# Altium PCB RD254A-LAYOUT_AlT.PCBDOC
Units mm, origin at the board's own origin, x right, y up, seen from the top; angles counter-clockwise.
Board outline 65 x 55 mm, 2 copper layers (TOP, BOTTOM), stack 0 mm thick; 28 components, 15 nets, 110 pads, 0 vias.
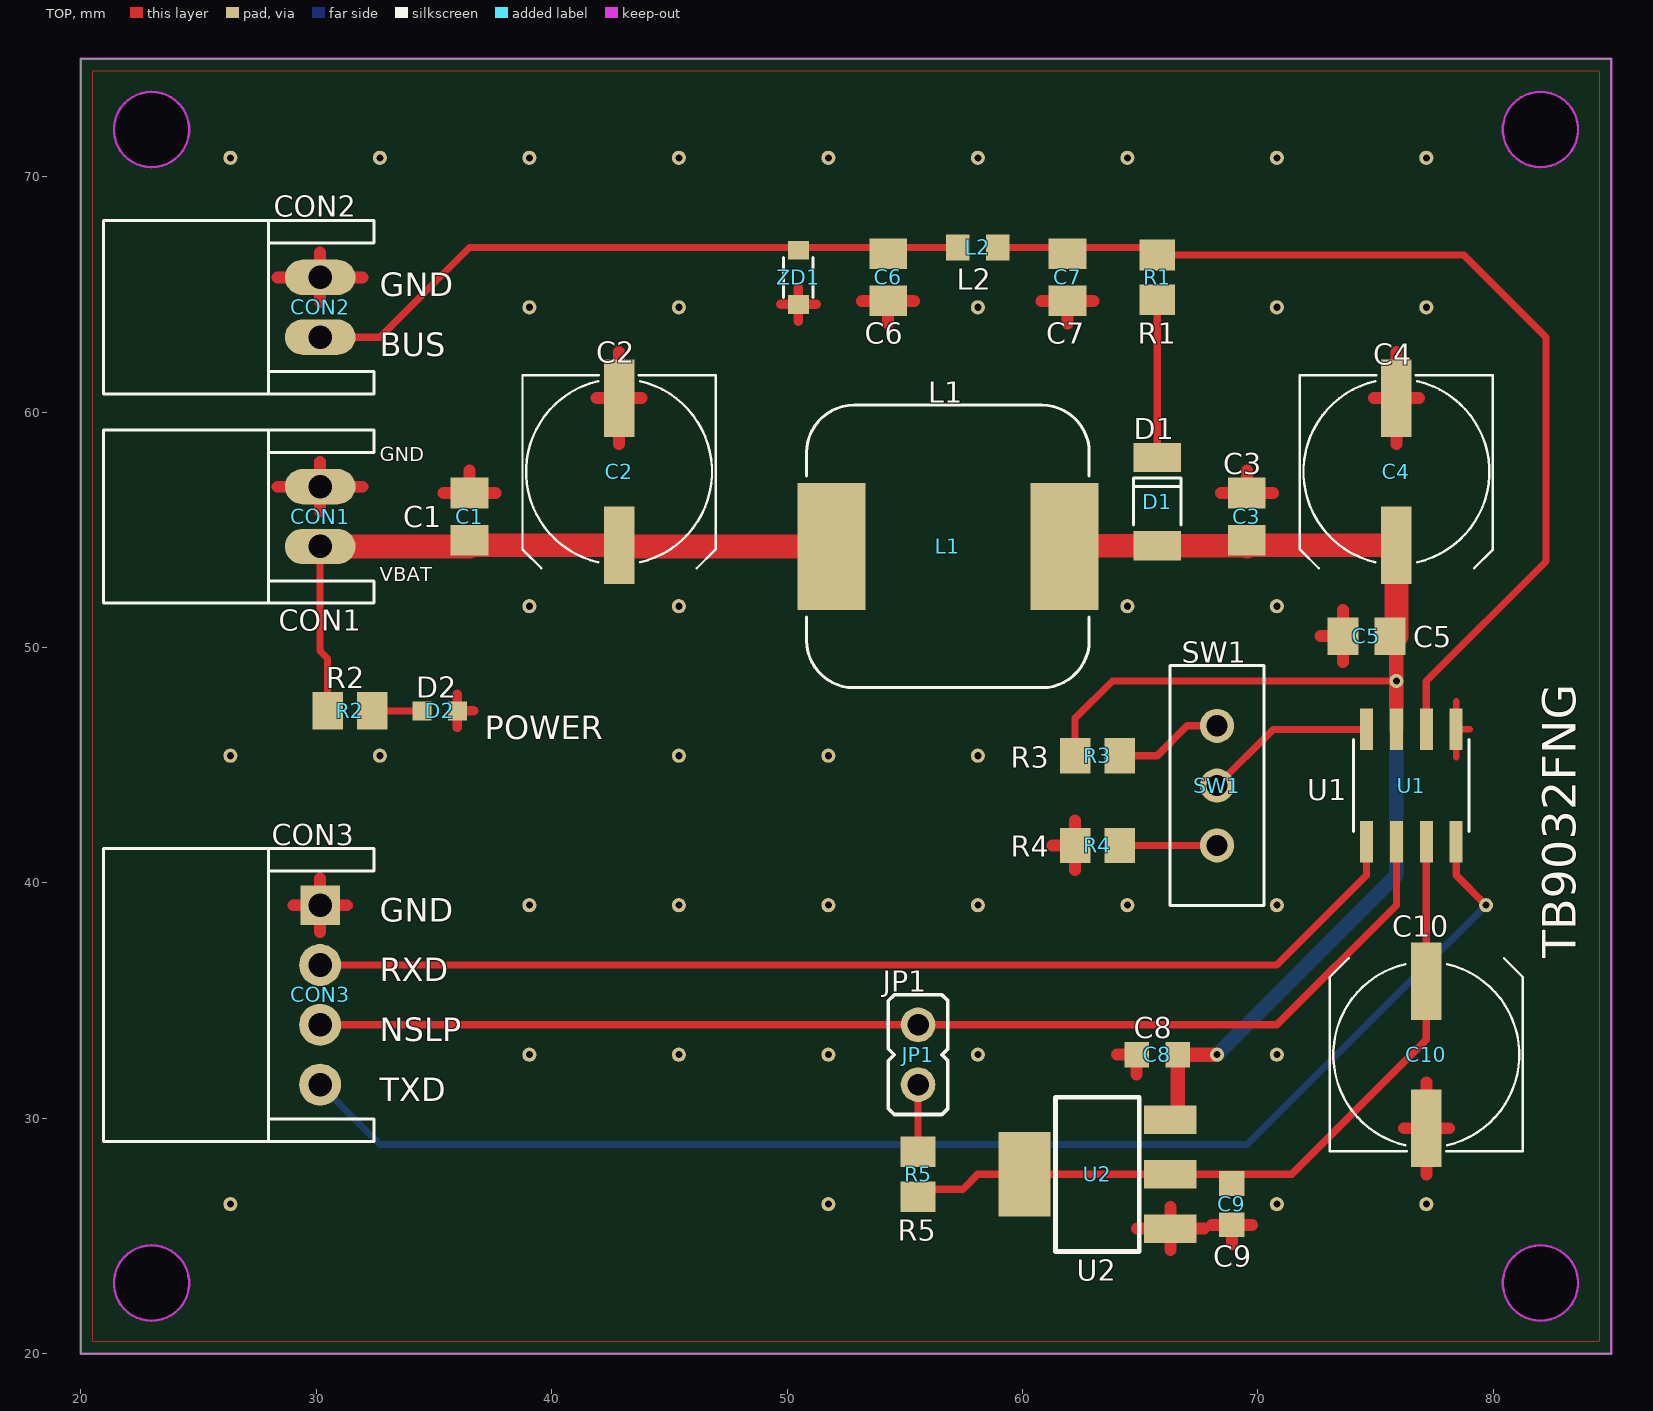
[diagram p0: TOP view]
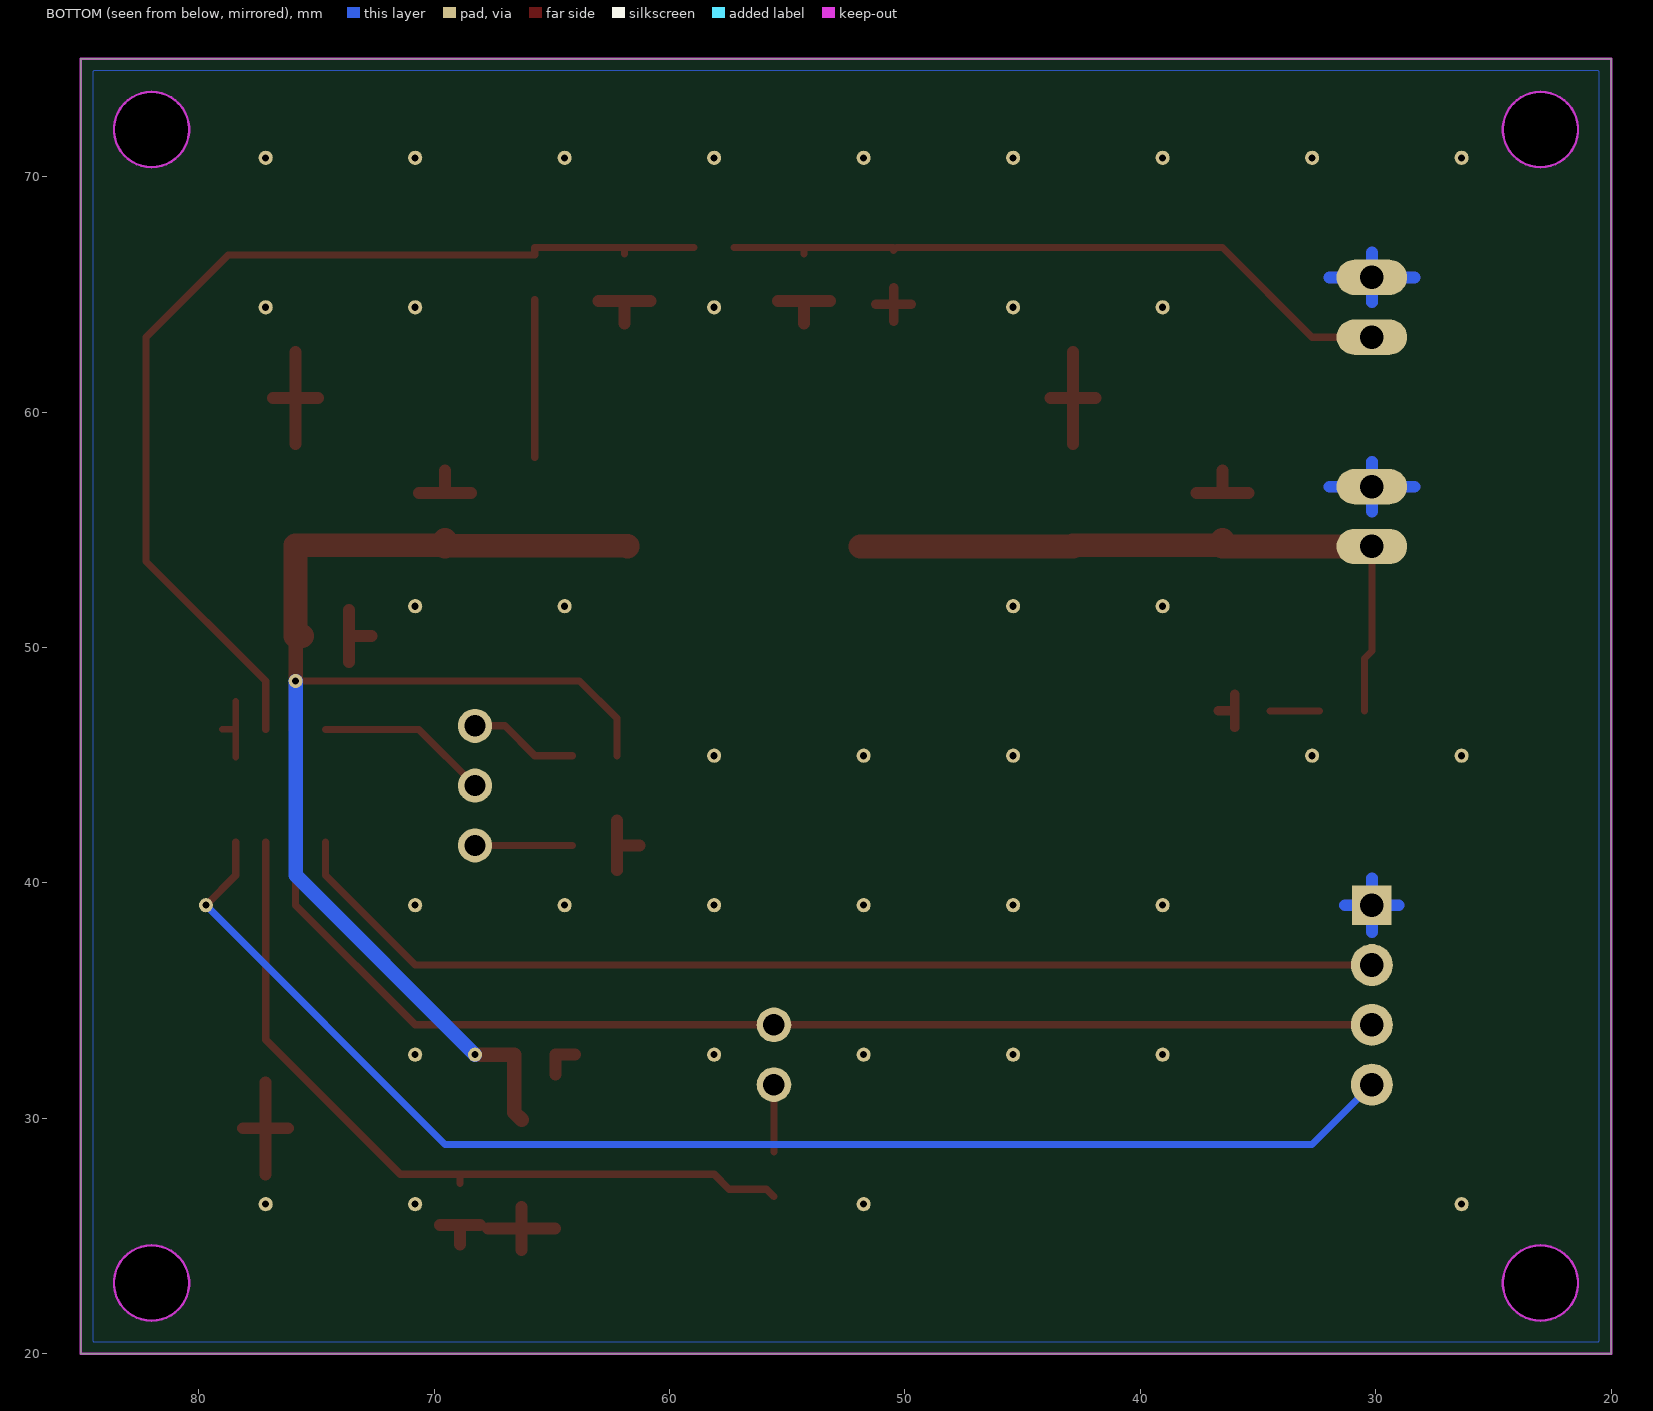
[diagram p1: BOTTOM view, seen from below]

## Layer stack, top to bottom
Top Solder: solder mask 0.0102, Solder Resist, Dk 3.5
TOP: signal copper (thickness not stored)
BOTTOM: signal copper (thickness not stored)
Bottom Solder: solder mask 0.0102, Solder Resist, Dk 3.5

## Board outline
20,20 20,75 85,75 85,20

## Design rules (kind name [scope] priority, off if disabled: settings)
AssemblyTestPointUsage [All] p0: scope1count=1 scope1_0_kind=Board scope1_0_value=Board scope2count=1 scope2_0_kind=Board scope2_0_value=Board commentlength=0
AssemblyTestpoint [All] p0: scope1count=1 scope1_0_kind=Board scope1_0_value=Board scope2count=1 scope2_0_kind=Board scope2_0_value=Board commentlength=0
Clearance [All] p0: scope1count=1 scope1_0_kind=Board scope1_0_value=Board scope2count=1 scope2_0_kind=Board scope2_0_value=Board commentlength=0 gap=0.254
Clearance [All] p1: gap=0.254 ignorepadtopadclearanceinfootprint=TRUE except(0.3: Arc-Hole Track-Hole SMDPad-Hole THPad-Hole Via-Hole Fill-Hole Poly-Hole Region-Hole Text-Hole)
ComponentClearance [All] p0: scope1count=1 scope1_0_kind=Board scope1_0_value=Board scope2count=1 scope2_0_kind=Board scope2_0_value=Board commentlength=0 gap=0.254 collisioncheckmode=3
DiffPairsRouting [All] p0: scope1count=1 scope1_0_kind=Board scope1_0_value=Board scope2count=1 scope2_0_kind=Board scope2_0_value=Board commentlength=0
FabricationTestPointUsage [All] p0: scope1count=1 scope1_0_kind=Board scope1_0_value=Board scope2count=1 scope2_0_kind=Board scope2_0_value=Board commentlength=0 valid=0 allowmultiple=FALSE
FabricationTestpoint [All] p0: scope1count=1 scope1_0_kind=Board scope1_0_value=Board scope2count=1 scope2_0_kind=Board scope2_0_value=Board commentlength=0 side=3 testpointundercomponent=TRUE minsize=1.016 maxsize=2.54 preferedsize=1.524 minholesize=0 maxholesize=1.016 preferedholesize=0.813 testpointgrid=0.025
FanoutControl Fanout_BGA [All] p0 off: scope1count=1 scope1_0_kind=Board scope1_0_value=Board scope2count=1 scope2_0_kind=Board scope2_0_value=Board commentlength=69 // Protel DXP Scope 1 Expression Was: IsBGA   Fanout_BGA (Default Rule)
FanoutControl Fanout_LCC [All] p0 off: scope1count=1 scope1_0_kind=Board scope1_0_value=Board scope2count=1 scope2_0_kind=Board scope2_0_value=Board commentlength=69 // Protel DXP Scope 1 Expression Was: IsLCC   Fanout_LCC (Default Rule)
FanoutControl Fanout_SOIC [All] p0 off: scope1count=1 scope1_0_kind=Board scope1_0_value=Board scope2count=1 scope2_0_kind=Board scope2_0_value=Board commentlength=71 // Protel DXP Scope 1 Expression Was: IsSOIC   Fanout_SOIC (Default Rule)
FanoutControl Fanout_Small [All] p0 off: scope1count=1 scope1_0_kind=Board scope1_0_value=Board scope2count=1 scope2_0_kind=Board scope2_0_value=Board commentlength=84 // Protel DXP Scope 1 Expression Was: (CompPinCount < 5)   Fanout_Small (Default Rule)
FanoutControl Fanout_Default [All] p0: scope1count=1 scope1_0_kind=Board scope1_0_value=Board scope2count=1 scope2_0_kind=Board scope2_0_value=Board commentlength=30 // Fanout_Default (Default Rule)
Height [All] p0: scope1count=1 scope1_0_kind=Board scope1_0_value=Board scope2count=1 scope2_0_kind=Board scope2_0_value=Board commentlength=0
HoleSize [All] p0: scope1count=1 scope1_0_kind=Board scope1_0_value=Board scope2count=1 scope2_0_kind=Board scope2_0_value=Board commentlength=0 absolutevalues=TRUE maxlimit=100 minlimit=0.001 maxpercent=80.000 minpercent=20.000
HoleSize [All] p1: absolutevalues=TRUE maxlimit=100 minlimit=0.001 maxpercent=80.000 minpercent=20.000
HoleToHoleClearance [All] p0: scope1count=1 scope1_0_kind=Board scope1_0_value=Board scope2count=1 scope2_0_kind=Board scope2_0_value=Board commentlength=0
HoleToHoleClearance [All] p1: gap=0.4 allowstackedmicrovias=FALSE
LayerPairs [All] p0: scope1count=1 scope1_0_kind=Board scope1_0_value=Board scope2count=1 scope2_0_kind=Board scope2_0_value=Board commentlength=0 enforce=TRUE
MinimumSolderMaskSliver [All] p0: scope1count=1 scope1_0_kind=Board scope1_0_value=Board scope2count=1 scope2_0_kind=Board scope2_0_value=Board commentlength=0
MinimumSolderMaskSliver [All] p1: minsoldermaskwidth=0.1
NetAntennae [All] p0: scope1count=1 scope1_0_kind=Board scope1_0_value=Board scope2count=1 scope2_0_kind=Board scope2_0_value=Board commentlength=0
NetAntennae [All] p1: netantennaetolerance=100
PasteMaskExpansion [All] p0: scope1count=1 scope1_0_kind=Board scope1_0_value=Board scope2count=1 scope2_0_kind=Board scope2_0_value=Board commentlength=0 expansion=0
PlaneClearance [All] p0: scope1count=1 scope1_0_kind=Board scope1_0_value=Board scope2count=1 scope2_0_kind=Board scope2_0_value=Board commentlength=0 clearance=0.001
PlaneClearance [All] p1: clearance=0.001
PlaneConnect [All] p0: scope1count=1 scope1_0_kind=Board scope1_0_value=Board scope2count=1 scope2_0_kind=Board scope2_0_value=Board commentlength=0 planeconnectstyle=Direct reliefexpansion=0.508 reliefentries=4 reliefconductorwidth=0.254 reliefairgap=0.254
PlaneConnect [All] p1: planeconnectstyle=Direct reliefexpansion=0.508 reliefentries=4 reliefconductorwidth=0.254 reliefairgap=0.254
PolygonConnect [All] p0: scope1count=1 scope1_0_kind=Board scope1_0_value=Board scope2count=1 scope2_0_kind=Board scope2_0_value=Board commentlength=0 connectstyle=Direct reliefconductorwidth=0.254 reliefentries=4 polygonreliefangle="90 Angle"
PolygonConnect [All] p1: connectstyle=Direct reliefconductorwidth=0.254 reliefentries=4 polygonreliefangle="90 Angle" airgapwidth=0.254
RoutingCorners [All] p0: scope1count=1 scope1_0_kind=Board scope1_0_value=Board scope2count=1 scope2_0_kind=Board scope2_0_value=Board commentlength=0 cornerstyle=45-Degree minsetback=2.54 maxsetback=2.54
RoutingLayers [All] p0: scope1count=1 scope1_0_kind=Board scope1_0_value=Board scope2count=1 scope2_0_kind=Board scope2_0_value=Board commentlength=0 top layer=Automatic bottom layer=Automatic
RoutingPriority [All] p0: scope1count=1 scope1_0_kind=Board scope1_0_value=Board scope2count=1 scope2_0_kind=Board scope2_0_value=Board commentlength=0
RoutingTopology [All] p0: scope1count=1 scope1_0_kind=Board scope1_0_value=Board scope2count=1 scope2_0_kind=Board scope2_0_value=Board commentlength=0 topology=Shortest
RoutingVias [All] p0: scope1count=1 scope1_0_kind=Board scope1_0_value=Board scope2count=1 scope2_0_kind=Board scope2_0_value=Board commentlength=0 holewidth=0.1 width=0.1 viastyle="Through Hole" minholewidth=0.001 minwidth=0.001 maxholewidth=100 maxwidth=100
RoutingVias [All] p1: holewidth=0.1 width=0.1 viastyle="Through Hole" minholewidth=0.001 minwidth=0.001 maxholewidth=100 maxwidth=100
ShortCircuit [All] p0: scope1count=1 scope1_0_kind=Board scope1_0_value=Board scope2count=1 scope2_0_kind=Board scope2_0_value=Board commentlength=0 allowed=FALSE
SilkToBoardRegionClearance [All] p0: scope1count=1 scope1_0_kind=Board scope1_0_value=Board scope2count=1 scope2_0_kind=Board scope2_0_value=Board commentlength=0
SilkToSilkClearance [All] p0: scope1count=1 scope1_0_kind=Board scope1_0_value=Board scope2count=1 scope2_0_kind=Board scope2_0_value=Board commentlength=0
SilkToSilkClearance [All] p1: silktosilkclearance=0.001
SilkToSolderMaskClearance [All] p0 off: scope1count=1 scope1_0_kind=Board scope1_0_value=Board scope2count=1 scope2_0_kind=Board scope2_0_value=Board commentlength=44 // Protel DXP Scope 1 Expression Was: IsPad
SilkToSolderMaskClearance [IsPad] p1: minsilkscreentomaskgap=0 clearancetoexposedcopper=TRUE
SolderMaskExpansion [All] p0: scope1count=1 scope1_0_kind=Board scope1_0_value=Board scope2count=1 scope2_0_kind=Board scope2_0_value=Board commentlength=0 expansion=0.001
SolderMaskExpansion [All] p1: expansion=0.001
UnRoutedNet [All] p0: scope1count=1 scope1_0_kind=Board scope1_0_value=Board scope2count=1 scope2_0_kind=Board scope2_0_value=Board commentlength=0
UnpouredPolygon [All] p0: scope1count=1 scope1_0_kind=Board scope1_0_value=Board scope2count=1 scope2_0_kind=Board scope2_0_value=Board commentlength=0
Width [All] p0: scope1count=1 scope1_0_kind=Board scope1_0_value=Board scope2count=1 scope2_0_kind=Board scope2_0_value=Board commentlength=0 maxlimit=1000 minlimit=2539.975 preferedwidth=0
Width [All] p1: maxlimit=1000 minlimit=2539.975 preferedwidth=0 toplayer_minwidth=0 bottomlayer_minwidth=0 minimp=50.000000 maximp=50.000000 favimp=50.000000
22 further rules are at their usual default settings.

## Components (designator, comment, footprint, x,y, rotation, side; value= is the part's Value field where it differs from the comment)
C1 "C0805K" C0805K 36.51,55.56 r90 top
C2 "UD-8X10_NICHICON_01" UD-8X10_NICHICON_01 42.86,57.465 r270 top
C3 "C0805K" C0805K 69.53,55.56 r90 top
C4 "UD-8X10_NICHICON_01" UD-8X10_NICHICON_01 75.88,57.465 r270 top
C5 "C0805K" C0805K 74.61,50.48 r180 top
C6 "C0805K" C0805K 54.29,65.72 r270 top
C7 "C0805K" C0805K 61.91,65.72 r270 top
C8 "C0603K" C0603K 65.72,32.7 r0 top
C9 "C0603K" C0603K 68.895,26.35 r90 top
C10 "UD-8X10_NICHICON_01" UD-8X10_NICHICON_01 77.15,32.7 r90 top
cam2 "A4L-LOC" A4L-LOC -68,-49 r0 top
CON1 "S2B-XH-A" S2B-XH-A 30.16,55.56 r90 top
CON2 "S2B-XH-A" S2B-XH-A 30.16,64.45 r90 top
CON3 "S4B-XH-A" S4B-XH-A 30.16,35.24 r90 top
D1 "LL4148" LL4148 65.72,56.195 r90 top
D2 "CHIP-LED0603" CHIP-LED0603 35.24,47.305 r270 top
JP1 "JP1" JP1 55.56,32.7 r0 top
L1 "7447709222" 7447709222 56.83,54.29 r270 top
L2 "R0603" R0603 58.1,66.99 r0 top
R1 "R0805" R0805 65.72,65.72 r270 top
R2 "M0805" M0805 31.43,47.305 r180 top
R3 "R0805" R0805 63.18,45.4 r0 top
R4 "R0805" R0805 63.18,41.59 r180 top
R5 "R0805" R0805 55.56,27.62 r90 top
SW1 "SS-12SDP2" SS-12SDP2 68.26,44.13 r0 top
U1 "P-SOP8-0405-1_27-002" P-SOP8-0405-1_27-002 76.515,44.13 r90 top
U2 "SOT223" SOT223 63.18,27.62 r90 top
ZD1 "USC" USC 50.48,65.72 r270 top

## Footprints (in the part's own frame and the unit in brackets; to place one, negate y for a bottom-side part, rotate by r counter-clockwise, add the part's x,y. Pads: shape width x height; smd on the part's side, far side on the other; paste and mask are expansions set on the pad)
7447709222 [mm] "KC00080BKP"
  rect 5.4x2.9 smd paste-5.603 mask+0: 1(0,-4.95) 2(0,4.95)
  silkscreen extent -6,-6 6,6
A4L-LOC [mm] "KC00080BKP"
C0603K [mm] "KC00080BKP"
  rect 1.05x1.08 smd paste-1.283 mask+0: 1(-0.875,0) 2(0.875,0)
C0805K [mm] "KC00080BKP"
  rect 1.3x1.6 smd paste-1.803 mask+0: 1(-1,0) 2(1,0)
CHIP-LED0603 [mm] "KC00080BKP"
  rect 0.8x0.8 smd paste-1.003 mask+0: A(0,-0.75) C(0,0.75)
JP1 [mm] "KC00080BKP"
  round 1.47 / inner round 0 / far side round 1.47 hole 0.914 paste-1.67 mask+0: 1(0,-1.27) 2(0,1.27)
  silkscreen extent -1.27,-2.54 1.27,2.54
LL4148 [mm] "KC00080BKP"
  rect 1.25x2 smd paste-2.203 mask+0: A(-1.875,0) K(1.875,0)
  silkscreen extent -1,-1 1,1
M0805 [mm] "KC00080BKP"
  rect 1.3x1.6 smd paste-1.803 mask+0: 1(-0.95,0) 2(0.95,0)
P-SOP8-0405-1_27-002 [mm] "KC00080BKP"
  rect 1.77x0.55 smd paste-1.973 mask+0: 1(-2.39,1.905) 2(-2.39,0.635) 3(-2.39,-0.635) 4(-2.39,-1.905) 5(2.39,-1.905) 6(2.39,-0.635) 7(2.39,0.635) 8(2.39,1.905)
  silkscreen extent -1.95,-2.45 1.95,2.45
R0603 [mm] "KC00080BKP"
  rect 1x1.1 smd paste-1.303 mask+0: 1(-0.85,0) 2(0.85,0)
R0805 [mm] "KC00080BKP"
  rect 1.3x1.5 smd paste-1.703 mask+0: 1(-0.95,0) 2(0.95,0)
S2B-XH-A [mm] "KC00080BKP"
  oval 1.5x3 / inner round 0 / far side oval 1.5x3 hole 1 paste-3.203 mask+0: 1(1.27,0) 2(-1.27,0)
  silkscreen extent -3.68,-2.3 3.68,9.2
S4B-XH-A [mm] "KC00080BKP"
  rect 1.676x1.676 / inner round 0 / far side rect 1.676x1.676 hole 1 paste-1.88 mask+0: 1(3.81,0)
  round 1.78 / inner round 0 / far side round 1.78 hole 1 paste-1.98 mask+0: 2(1.27,0) 3(-1.27,0) 4(-3.81,0)
  silkscreen extent -6.22,-2.3 6.22,9.2
SOT223 [mm] "KC00080BKP"
  rect 1.219x2.235 smd paste-2.438 mask+0: 1(-2.311,-3.099) 2(0,-3.099) 3(2.311,-3.099)
  rect 3.6x2.2 smd paste-3.803 mask+0: TAB(0,3.099)
  silkscreen extent -3.28,-1.78 3.28,1.78
SS-12SDP2 [mm] "KC00080BKP"
  round 1.45 / inner round 0 / far side round 1.45 hole 0.9 paste-1.65 mask+0: 1(0,2.54) 2(0,0) 3(0,-2.54)
  silkscreen extent -2,-5.1 2,5.1
UD-8X10_NICHICON_01 [mm] "KC00080BKP"
  rect 3.3x1.3 smd paste-3.503 mask+0: 1(-3.125,0) 2(3.125,0)
  silkscreen extent -4.1,-4.1 4.1,4.1
USC [mm] "KC00080BKP"
  rect 0.8x0.9 smd paste-1.103 mask+0: 1(-1.15,0) 2(1.15,0)
  silkscreen extent -0.85,-0.63 0.85,0.63

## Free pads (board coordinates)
  round 0 hole 3.2 unplated paste-3.4 mask+0: ""(23,23) ""(23,72) ""(82,23) ""(82,72)
  round 0.6 / inner round 0 / far side round 0.6 hole 0.3 paste-0.6 mask+0: ""(26.35,26.35) ""(26.35,45.4) ""(26.35,70.8) ""(32.7,45.4) ""(32.7,70.8) ""(39.05,32.7) ""(39.05,39.05) ""(39.05,51.75) ""(39.05,64.45) ""(39.05,70.8) ""(45.4,32.7) ""(45.4,39.05) ""(45.4,45.4) ""(45.4,51.75) ""(45.4,64.45) ""(45.4,70.8) ""(51.75,26.35) ""(51.75,32.7) ""(51.75,39.05) ""(51.75,45.4) ""(51.75,70.8) ""(58.1,32.7) ""(58.1,39.05) ""(58.1,45.4) ""(58.1,64.45) ""(58.1,70.8) ""(64.45,39.05) ""(64.45,51.75) ""(64.45,70.8) ""(68.26,32.7) ""(70.8,26.35) ""(70.8,32.7) ""(70.8,39.05) ""(70.8,51.75) ""(70.8,64.45) ""(70.8,70.8) ""(75.88,48.575) ""(77.15,26.35) ""(77.15,64.45) ""(77.15,70.8) ""(79.69,39.05)

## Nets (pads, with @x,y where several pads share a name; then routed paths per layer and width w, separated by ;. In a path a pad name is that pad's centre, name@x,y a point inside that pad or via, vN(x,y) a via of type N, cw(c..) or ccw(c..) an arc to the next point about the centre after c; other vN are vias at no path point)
+5V: C9.2 C10.2 R5.1 U1.3 U2.2 U2.TAB | length 33.2
  TOP w0.305: R5.1 55.875,26.985 57.465,26.985 58.1,27.62 U2.TAB U2.2 C9.2@68.895,27.62 ; C9.2 C9.2@68.895,27.62 ; U1.3 C10.2 77.15,33.335 71.435,27.62 C9.2@68.895,27.62
+12V: C1.1 C2.2 CON1.2 L1.1 R2.2 | length 29.2
  TOP w0.305: CON1.2 30.16,49.845 30.48,49.525 R2.2
  TOP w1.016: CON1.2 36.51,54.29 C1.1@36.51,54.34 ; C1.1 C1.1@36.51,54.34 ; L1.1 42.86,54.29 C2.2 C1.1@36.51,54.34
BUS: C7.1 L2.2 R1.1 U1.6 | length 44.1
  TOP w0.305: L2.2 C7.1@61.91,66.99 ; C7.1 C7.1@61.91,66.99 ; U1.6 77.15,48.575 82.23,53.655 82.23,63.18 78.74,66.67 R1.1 65.72,66.99 C7.1@61.91,66.99
GND: C1.2 C2.1 C3.2 C4.1 C5.2 C6.2 C7.2 C8.1 C9.1 C10.1 CON1.1 CON2.1 CON3.1 D2.C pad.@26.35,26.35 pad.@26.35,45.4 pad.@26.35,70.8 pad.@32.7,45.4 pad.@32.7,70.8 pad.@39.05,32.7 pad.@39.05,39.05 pad.@39.05,51.75 pad.@39.05,64.45 pad.@39.05,70.8 pad.@45.4,32.7 pad.@45.4,39.05 pad.@45.4,45.4 pad.@45.4,51.75 pad.@45.4,64.45 pad.@45.4,70.8 pad.@51.75,26.35 pad.@51.75,32.7 pad.@51.75,39.05 pad.@51.75,45.4 pad.@51.75,70.8 pad.@58.1,32.7 pad.@58.1,39.05 pad.@58.1,45.4 pad.@58.1,64.45 pad.@58.1,70.8 pad.@64.45,39.05 pad.@64.45,51.75 pad.@64.45,70.8 pad.@70.8,26.35 pad.@70.8,32.7 pad.@70.8,39.05 pad.@70.8,51.75 pad.@70.8,64.45 pad.@70.8,70.8 pad.@77.15,26.35 pad.@77.15,64.45 pad.@77.15,70.8 R4.2 U1.5 U2.1 ZD1.2 | length 85.2
  TOP w0.275: 78.42,45.33 U1.5 ; 78.42,47.71 U1.5 ; 79,46.52 U1.5
  TOP w0.4: 35.99,46.6 D2.C ; 35.99,48.01 D2.C ; 36.695,47.305 D2.C ; 49.725,64.57 ZD1.2 ; 50.48,63.865 ZD1.2 ; 50.48,65.275 ZD1.2 ; 51.235,64.57 ZD1.2
  TOP w0.5: 28.355,56.83 CON1.1 ; 28.355,65.72 CON2.1 ; 29.017,39.05 CON3.1 ; 30.16,37.907 CON3.1 ; 30.16,40.193 CON3.1 ; 30.16,55.775 CON1.1 ; 30.16,57.885 CON1.1 ; 30.16,64.665 CON2.1 ; 30.16,66.775 CON2.1 ; 31.303,39.05 CON3.1 ; 31.965,56.83 CON1.1 ; 31.965,65.72 CON2.1
  TOP w0.508: 35.405,56.56 C1.2 ; 36.51,57.515 C1.2 ; 37.615,56.56 C1.2 ; 41.905,60.59 C2.1 ; 42.86,58.635 C2.1 ; 42.86,62.545 C2.1 ; 43.815,60.59 C2.1 ; 53.185,64.72 C6.2 ; 54.29,63.765 C6.2 ; 55.395,64.72 C6.2 ; 60.805,64.72 C7.2 ; 61.275,41.59 R4.2 ; 61.91,63.765 C7.2 ; 62.23,40.535 R4.2 ; 62.23,42.645 R4.2 ; 63.015,64.72 C7.2 ; 64.015,32.7 C8.1 64.845,31.855 ; 64.856,25.309 U2.1 ; 66.279,24.395 U2.1 ; 66.279,26.224 U2.1 ; 67.702,25.309 U2.1 ; 68.05,25.475 C9.1 ; 68.425,56.56 C3.2 ; 68.895,24.645 C9.1 ; 69.53,57.515 C3.2 ; 69.74,25.475 C9.1 ; 70.635,56.56 C3.2 ; 72.655,50.48 C5.2 ; 73.61,49.375 C5.2 ; 73.61,51.585 C5.2 ; 74.925,60.59 C4.1 ; 75.88,58.635 C4.1 ; 75.88,62.545 C4.1 ; 76.195,29.575 C10.1 ; 76.835,60.59 C4.1 ; 77.15,27.62 C10.1 ; 77.15,31.53 C10.1 ; 78.105,29.575 C10.1
  BOTTOM w0.5: 28.355,56.83 CON1.1 ; 28.355,65.72 CON2.1 ; 29.017,39.05 CON3.1 ; 30.16,37.907 CON3.1 ; 30.16,40.193 CON3.1 ; 30.16,55.775 CON1.1 ; 30.16,57.885 CON1.1 ; 30.16,64.665 CON2.1 ; 30.16,66.775 CON2.1 ; 31.303,39.05 CON3.1 ; 31.965,56.83 CON1.1 ; 31.965,65.72 CON2.1
N_1: D1.K R1.2 | length 6.7
  TOP w0.305: D1.K R1.2
N_2: SW1.2 U1.8 | length 7.3
  TOP w0.305: SW1.2 70.65,46.52 U1.8
N_3: JP1.1 R5.2 | length 2.9
  TOP w0.305: R5.2 JP1.1
N_14: R3.2 SW1.1 | length 4.7
  TOP w0.305: R3.2 65.72,45.4 66.99,46.67 SW1.1
N_15: R4.1 SW1.3 | length 4.1
  TOP w0.305: R4.1 SW1.3
N_30: D2.A R2.1 | length 2.1
  TOP w0.305: R2.1 D2.A
N_41: C6.1 CON2.2 L2.1 ZD1.1 | length 29.1
  TOP w0.305: CON2.2 32.7,63.18 36.51,66.99 50.36,66.99 ZD1.1 50.48,66.99 C6.1@54.29,66.99 ; C6.1 C6.1@54.29,66.99 ; L2.1 C6.1@54.29,66.99
NSLP: CON3.3 JP1.2 U1.2 | length 50.5
  TOP w0.305: CON3.3 JP1.2 70.8,33.97 75.88,39.05 U1.2
RXD: CON3.2 U1.1 | length 47.4
  TOP w0.305: CON3.2 70.8,36.51 74.61,40.32 U1.1
TXD: CON3.4 pad.@79.69,39.05 U1.4 | length 58
  TOP w0.305: U1.4 78.42,40.32 pad.@79.69,39.05
  BOTTOM w0.305: CON3.4 32.7,28.89 69.53,28.89 pad.@79.69,39.05
VBAT: C3.1 C4.2 C5.1 C8.2 D1.A L1.2 pad.@68.26,32.7 pad.@75.88,48.575 R3.1 U1.7 U2.3 | length 62.1
  TOP w0.305: R3.1 62.23,46.99 63.815,48.575 pad.@75.88,48.575
  TOP w0.61: U2.3 66.595,30.247 C8.2 pad.@68.26,32.7 ; C5.1 75.88,50.21 75.88,48.575 U1.7
  TOP w1.016: L1.2 61.78,54.32 D1.A C3.1@69.53,54.32 ; C3.1@69.53,54.29 C3.1@69.53,54.32 ; C3.1 C3.1@69.53,54.34 ; C5.1 75.88,50.48 C4.2 C3.1@69.53,54.34 ; C3.1@69.53,54.32 C3.1@69.53,54.34
  BOTTOM w0.61: pad.@68.26,32.7 75.88,40.32 pad.@75.88,48.575

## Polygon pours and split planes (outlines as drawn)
GND on BOTTOM "BOTTOM2" (solid, pour order 2): 20.575,20.5 cw(c20.575,20.575) 20.5,20.575 20.5,74.425 cw(c20.575,74.425) 20.575,74.5 84.425,74.5 cw(c84.425,74.425) 84.5,74.425 84.5,20.575 cw(c84.425,20.575) 84.425,20.5
GND on TOP "TOP1" (solid, pour order 3): 20.575,20.5 cw(c20.575,20.575) 20.5,20.575 20.5,74.425 cw(c20.575,74.425) 20.575,74.5 84.425,74.5 cw(c84.425,74.425) 84.5,74.425 84.5,20.575 cw(c84.425,20.575) 84.425,20.5

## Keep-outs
Keep-Out Layer:
  lines w0.1: 20,20 20,75 85,75 85,20 20,20 ; 23,21.4 cw(c23,23) 23,24.6 cw(c23,23) 23,21.4 ; 23,70.4 cw(c23,72) 23,73.6 cw(c23,72) 23,70.4 ; 82,21.4 cw(c82,23) 82,24.6 cw(c82,23) 82,21.4 ; 82,70.4 cw(c82,72) 82,73.6 cw(c82,72) 82,70.4

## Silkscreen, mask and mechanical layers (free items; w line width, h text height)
Top Overlay:
  text "GND" at 32.7,64.92 h0.99
  text "BUS" at 32.7,62.38 h0.99
  text "GND" at 32.7,57.9 h0.61
  text "VBAT" at 32.7,52.82 h0.61
  text "POWER" at 37.145,46.105 h0.99
  text "GND" at 32.7,38.35 h0.99
  text "TB9032FNG" at 83.5,36.8 h1.42 r90
  text "RXD" at 32.7,35.81 h0.99
  text "NSLP" at 32.7,33.27 h0.99
  text "TXD" at 32.7,30.73 h0.99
